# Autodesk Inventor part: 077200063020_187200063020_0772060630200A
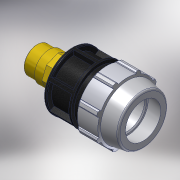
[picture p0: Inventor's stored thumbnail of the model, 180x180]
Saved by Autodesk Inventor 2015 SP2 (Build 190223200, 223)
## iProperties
Created: 2017-02
Part Number: 077200063020_187200063020_0772060630200A
Material: PVC-Piping
Description: PLASSON MALE ADAPTOR INTEGRAL BRASS THREAD 63-2"
Document SubType Name: Modeling
Designer: KIM
Mass: 92.6774 g
Surface Area: 199.44 cm^2
Volume: 66.1981 cm^3
Density: 1.4 g/cm^3
Appearance: PTFE
Author: KIM
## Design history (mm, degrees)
derived "07720.ipt"
feature "Solid1::07720.ipt"
tag "TaggingFeature1"
body "Solid1"
other parameters: "d2" = 63, "d4" = 27.71429, "d5" = 27.71429, "d7" = 113, "d8" = 84.75, "d9" = 27.71429, "d11" = 5.54286, "d12" = 90.4, "d13" = 120 deg, "d14" = 88.2, "d15" = 10 deg, "d16" = 101.7, "d18" = 3.15, "d19" = 35 deg, "d20" = 17.5 deg, "d21" = 105.09, "d23" = 0, "d25" = 360 deg, "d27" = 2.26, "d34" = 5.65, "d36" = 0, "d42" = 38.8, "d43" = 3.39, "d46" = 1.89, "d49" = 123, "d51" = 194, "d53" = 1.26, "d55" = 360 deg, "d59" = 38.8, "d60" = 59.614, "d61" = 65.5754, "d62" = 26, "d63" = 64.66667, "d64" = 41.7298, "d65" = 194, "d66" = 21.13491, "d67" = 0, "d68" = 1.26, "d71" = 30 deg, "d72" = 53.6526, "d_" = 63, "E_" = 113, "H_" = 194, "l_" = 123, "l_2" = 26, "R_" = 59.614, "d73" = 35.22485
